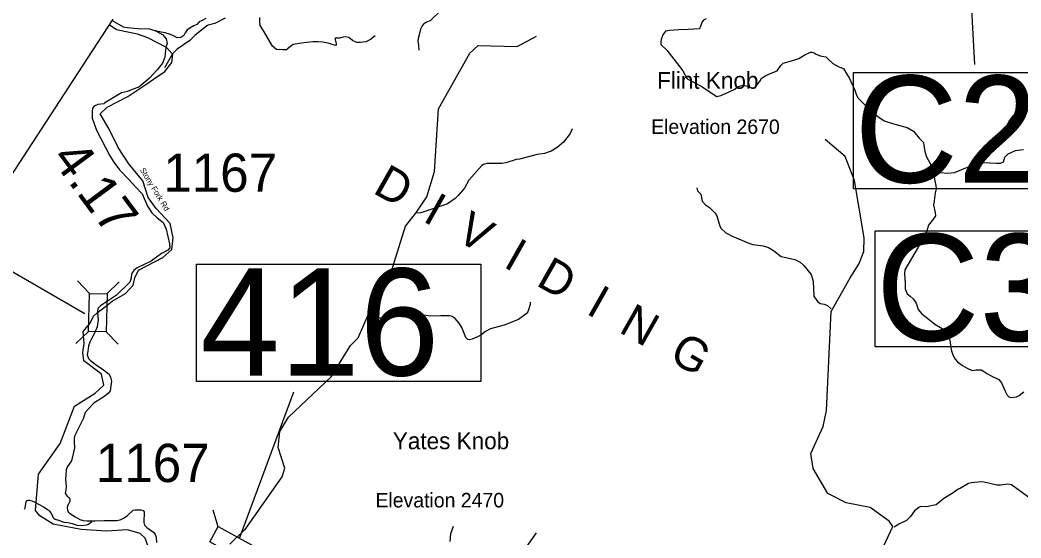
# Model space of a CAD drawing. Extents: x 1248224 to 1454986, y 825081 to 985870.
# Drawn here: x 1271332 to 1284414, y 889575 to 896350 of the extents above; entities that cross this region are included whole.
import ezdxf

# ---------------------------------------------------------------- set-up
doc = ezdxf.new("R2010")
doc.units = 0
for name, color, linetype in [('Exist Boundary Political CountyLine', 7, 'Continuous'), ('Exist Geographical Mountain Summit Elevation Number Label', 7, 'Continuous'), ('Exist Geographical Mountain Summit Label', 7, 'Continuous'), ('Exist Hydrographic Creek Single Shore', 7, 'Continuous'), ('Exist Hydrographic Misc Water Feature', 7, 'Continuous'), ('Exist Road Non-System Type 51', 7, 'Continuous'), ('Exist Road Primary US Structure Culvert Number Label', 7, 'Continuous'), ('Exist Road Secondary Mileage Hundredths English Label', 7, 'Continuous'), ('Exist Road Secondary Structure Standard Bridge CELL', 7, 'Continuous'), ('Exist Road Secondary Structure Standard Bridge Number Label', 7, 'Continuous'), ('Exist Road Secondary Type 41 Attributed', 7, 'Continuous'), ('Exist Road Secondary Type 51 Label', 7, 'Continuous'), ('Exist Road Secondary Type 51 Number Label', 7, 'Continuous')]:
    doc.layers.add(name, color=color, linetype=linetype)

msp = doc.modelspace()

# ---------------------------------------------------------------- linework, layer by layer
at = {"layer": 'Exist Boundary Political CountyLine'}
msp.add_lwpolyline([(1272546, 896361), (1272209, 895845), (1272087, 895657), (1271079, 894112), (1270645, 893445), (1270071, 892565), (1269839, 892212), (1269310, 891394), (1268930, 890816), (1268447, 890082), (1267988, 889389), (1267175, 888171), (1266759, 887546), (1266505, 887166), (1265873, 886219), (1264802, 884614), (1263985, 883390), (1262147, 880635), (1261769, 880070), (1260071, 878961), (1254161, 875151), (1250985, 873104), (1248224, 871303)], dxfattribs=at)
at = {"layer": 'Exist Hydrographic Creek Single Shore'}
for points in [[(1273331, 895899), (1273248, 895990), (1273003, 896117), (1272866, 896164), (1272593, 896221), (1272496, 896285)], [(1272882, 893076), (1273200, 893243), (1273317, 893347), (1273332, 893499), (1273293, 893688), (1273113, 893884), (1273008, 894027), (1272938, 894248), (1272752, 894469), (1272615, 894681), (1272496, 894923), (1272379, 895121), (1272472, 895208), (1272739, 895351), (1272991, 895514), (1273074, 895574), (1273226, 895677), (1273316, 895794), (1273331, 895899), (1273244, 895992)], [(1282587, 889398), (1282737, 889726), (1282689, 889796), (1282443, 889975), (1282128, 890034), (1281889, 890157), (1281697, 890486), (1281668, 890680), (1281827, 891035), (1281874, 891241), (1281931, 892539), (1282183, 892978), (1282296, 893156), (1282359, 893322), (1282363, 893499), (1282240, 894250), (1282114, 894565), (1281853, 894786)], [(1272346, 892523), (1272429, 892584), (1272538, 892672), (1272711, 892774), (1272810, 892882), (1272832, 892976), (1272882, 893076)], [(1272165, 891894), (1272154, 892000), (1272172, 892118), (1272159, 892276), (1272250, 892385), (1272293, 892478), (1272346, 892523)], [(1273750, 889148), (1273089, 889381), (1273008, 889465), (1272969, 889574), (1272903, 889634), (1272738, 889680), (1272462, 889663), (1272129, 889686), (1271764, 889756), (1271592, 889867), (1271535, 889934), (1271572, 890410), (1271857, 890811), (1272044, 891300), (1272315, 891468), (1272426, 891573), (1272396, 891716), (1272165, 891894)], [(1274075, 889493), (1274272, 889686), (1274274, 889688)]]:
    msp.add_lwpolyline(points, dxfattribs=at)
at = {"layer": 'Exist Hydrographic Misc Water Feature'}
for points in [[(1274011, 896376), (1273877, 896304), (1273792, 896284), (1273772, 896272), (1273615, 896148), (1273553, 896080), (1273386, 895970), (1273326, 895907), (1273218, 895724)], [(1274274, 889688), (1274756, 890375), (1274792, 890490), (1274707, 890757), (1274729, 890967), (1274842, 891155), (1275397, 891685), (1275649, 892094), (1275751, 892194), (1275885, 892502), (1276145, 892925), (1276371, 893652), (1276504, 893822), (1276647, 894037), (1276747, 894370), (1276801, 895186), (1277211, 895917), (1277321, 896016), (1277830, 896003), (1278083, 896139)], [(1284168, 894898), (1284229, 894967), (1284253, 895017), (1284315, 895101), (1284498, 895214)], [(1284168, 894898), (1284229, 894967), (1284253, 895017), (1284315, 895101), (1284498, 895214)], [(1278548, 894926), (1278523, 894867), (1278434, 894751), (1278352, 894681), (1278275, 894635), (1278186, 894603), (1278090, 894589), (1277860, 894529), (1277818, 894526), (1277681, 894483), (1277628, 894472), (1277432, 894471), (1277388, 894461), (1277368, 894449), (1277197, 894255), (1277142, 894152), (1277060, 894056), (1277019, 894017), (1276919, 893947), (1276883, 893931), (1276572, 893828), (1276504, 893822)], [(1280177, 894156), (1280188, 894116), (1280230, 894070), (1280248, 893980), (1280289, 893933), (1280344, 893896), (1280415, 893824), (1280438, 893787), (1280477, 893654), (1280496, 893625), (1280558, 893568), (1280637, 893522), (1280855, 893431), (1280909, 893413), (1281045, 893398), (1281112, 893376), (1281179, 893337), (1281281, 893258), (1281456, 893216), (1281528, 893182), (1281577, 893137), (1281670, 893022), (1281696, 892934), (1281705, 892738), (1281755, 892668), (1281791, 892643), (1281842, 892634), (1281886, 892617), (1281935, 892571)], [(1278000, 892660), (1277998, 892628), (1277967, 892535), (1277947, 892508), (1277845, 892434), (1277661, 892360), (1277480, 892311), (1277415, 892276), (1277353, 892227), (1277303, 892201), (1277240, 892175), (1277204, 892167), (1277184, 892172), (1277156, 892197), (1277104, 892330), (1277073, 892386), (1277020, 892444), (1276981, 892471), (1276945, 892480), (1276833, 892482), (1276697, 892476), (1276577, 892495), (1276485, 892485), (1276412, 892461), (1276269, 892472), (1276164, 892469), (1276036, 892452), (1276012, 892453), (1275992, 892461), (1275941, 892494), (1275885, 892502)], [(1284593, 890047), (1284288, 890272), (1284240, 890281), (1284148, 890266), (1284100, 890267), (1283913, 890309), (1283853, 890307), (1283765, 890297), (1283728, 890286), (1283610, 890218), (1283594, 890215), (1283527, 890165), (1283405, 890090), (1283303, 890008), (1283178, 889981), (1283106, 889987), (1283078, 889975), (1283021, 889929), (1282969, 889856), (1282916, 889806), (1282819, 889756), (1282758, 889715)], [(1276992, 889725), (1276957, 889630), (1276947, 889530)], [(1276458, 885104), (1276385, 885740), (1276213, 886210), (1276217, 886377), (1276325, 886861), (1276414, 886915), (1276860, 887060), (1277285, 887393), (1277703, 887792), (1277945, 888119), (1278137, 888466), (1278132, 888614), (1278059, 888717), (1277895, 888822), (1277792, 889024), (1277797, 889241), (1278082, 889642)]]:
    msp.add_lwpolyline(points, dxfattribs=at)
at = {"layer": 'Exist Road Non-System Type 51'}
for points in [[(1277521, 896794), (1277396, 896813), (1277239, 896817), (1277112, 896800), (1277030, 896765), (1276969, 896720), (1276927, 896664), (1276899, 896624), (1276878, 896579), (1276843, 896514), (1276807, 896466), (1276794, 896436), (1276735, 896381), (1276691, 896341), (1276642, 896321), (1276605, 896295), (1276588, 896272), (1276567, 896230), (1276550, 896156), (1276536, 896107), (1276532, 896079), (1276541, 896018), (1276545, 895955)], [(1275975, 896142), (1275911, 896094), (1275850, 896065), (1275781, 896054), (1275734, 896056), (1275676, 896082), (1275627, 896122), (1275589, 896130), (1275553, 896124), (1275505, 896113), (1275482, 896113), (1275456, 896113), (1275448, 896100), (1275459, 896065), (1275465, 896031), (1275454, 896018), (1275412, 896031), (1275357, 896048), (1275290, 896060), (1275229, 896065), (1275160, 896065), (1275082, 896056), (1275012, 896048), (1274953, 896039), (1274903, 896029), (1274865, 896004), (1274829, 895974), (1274814, 895960), (1274764, 895960), (1274683, 895966), (1274633, 896008), (1274521, 896193), (1274471, 896279), (1274467, 896334), (1274467, 896384)], [(1273762, 896370), (1273711, 896345), (1273671, 896324), (1273642, 896292), (1273602, 896273), (1273551, 896244), (1273516, 896222), (1273492, 896182), (1273471, 896147), (1273433, 896122), (1273385, 896117), (1273345, 896138), (1273299, 896161), (1273229, 896182), (1273175, 896191), (1273101, 896208)], [(1280301, 896363), (1280264, 896347), (1280248, 896327), (1280223, 896269), (1280212, 896235), (1280064, 896226), (1279940, 896223), (1279819, 896214), (1279769, 896202), (1279734, 896155), (1279710, 896093), (1279707, 896066), (1279707, 896039), (1279710, 896025), (1279784, 895954), (1279937, 895759), (1279996, 895685), (1280050, 895581)], [(1280941, 895473), (1281009, 895558), (1281020, 895585), (1281077, 895623), (1281147, 895656), (1281227, 895685), (1281274, 895756), (1281307, 895786), (1281443, 895824), (1281511, 895848), (1281587, 895895), (1281664, 895928), (1281679, 895928), (1281711, 895922), (1281738, 895904), (1281788, 895883), (1281815, 895875), (1281865, 895866), (1281883, 895845), (1281956, 895783), (1282032, 895739), (1282094, 895715), (1282124, 895665), (1282174, 895585), (1282207, 895508), (1282236, 895446), (1282266, 895367), (1282286, 895328), (1282310, 895302), (1282381, 895231), (1282481, 895136), (1282555, 895077), (1282625, 895033), (1282734, 894998), (1282926, 894944), (1283008, 894894), (1283085, 894803), (1283138, 894749), (1283144, 894714), (1283156, 894631), (1283180, 894560), (1283221, 894484), (1283265, 894373)], [(1280050, 895581), (1280236, 895484), (1280439, 895351)], [(1280439, 895351), (1280489, 895363), (1280598, 895411), (1280675, 895446), (1280708, 895476), (1280746, 895490), (1280784, 895496), (1280840, 895485), (1280846, 895485), (1280870, 895470), (1280911, 895464), (1280941, 895473)], [(1283265, 894373), (1283360, 894354), (1283453, 894345), (1283546, 894354), (1283834, 894472), (1283910, 894485), (1284003, 894480), (1284092, 894476), (1284147, 894476), (1284185, 894497), (1284202, 894557), (1284248, 894599), (1284341, 894641), (1284447, 894658)], [(1283265, 894373), (1283288, 894246), (1283300, 894184), (1283306, 894140), (1283294, 894089), (1283277, 893986), (1283271, 893927), (1283294, 893832), (1283297, 893788), (1283271, 893750), (1283206, 893667), (1283182, 893590), (1283070, 893377), (1282896, 893081), (1282893, 893033), (1282899, 892909), (1282902, 892832), (1282928, 892767), (1282967, 892738), (1283005, 892702), (1283044, 892646), (1283070, 892563), (1283117, 892505), (1283197, 892446), (1283288, 892370), (1283362, 892328), (1283436, 892284), (1283462, 892254), (1283480, 892219), (1283480, 892175), (1283489, 892139), (1283492, 892083), (1283507, 892021), (1283524, 891971), (1283554, 891915), (1283583, 891878)], [(1283583, 891878), (1283648, 891830), (1283712, 891798), (1283774, 891768), (1283804, 891771), (1283828, 891774), (1283893, 891774), (1283937, 891748), (1283975, 891724), (1284025, 891697), (1284123, 891650), (1284158, 891606), (1284211, 891485), (1284235, 891443), (1284253, 891423), (1284282, 891414), (1284356, 891423), (1284392, 891440), (1284451, 891488)], [(1271390, 889953), (1271399, 889971), (1271405, 889999), (1271408, 890023), (1271410, 890049), (1271420, 890061), (1271437, 890070), (1271457, 890072), (1271484, 890061), (1271526, 890042), (1271572, 890017), (1271637, 889982), (1271698, 889945), (1271718, 889928), (1271733, 889906), (1271751, 889876), (1271762, 889848), (1271774, 889833), (1271792, 889821), (1271836, 889808), (1271903, 889783), (1271955, 889776), (1272011, 889763), (1272080, 889745), (1272132, 889740), (1272164, 889741), (1272201, 889747), (1272219, 889754), (1272271, 889791)]]:
    msp.add_lwpolyline(points, dxfattribs=at)
at = {"layer": 'Exist Road Primary US Structure Culvert Number Label'}
msp.add_line((1283619, 899049), (1283808, 895770), dxfattribs=at)
for points in [[(1282224, 895662), (1286206, 895662), (1286206, 894143), (1282224, 894143)], [(1282506, 893594), (1286488, 893594), (1286488, 892074), (1282506, 892074)]]:
    msp.add_lwpolyline(points, close=True, dxfattribs=at)
at = {"layer": 'Exist Road Secondary Structure Standard Bridge CELL'}
for p, q in [((1272239, 892774), (1272082, 892937)), ((1272465, 892768), (1272629, 892925)), ((1272063, 892121), (1272227, 892278)), ((1272615, 892109), (1272458, 892273)), ((1273921, 889722), (1273858, 889939))]:
    msp.add_line(p, q, dxfattribs=at)
for points in [[(1272227, 892278), (1272238, 892774), (1272469, 892768), (1272458, 892273)], [(1274244, 889283), (1273811, 889523), (1273923, 889725), (1274357, 889485)]]:
    msp.add_lwpolyline(points, close=True, dxfattribs=at)
at = {"layer": 'Exist Road Secondary Structure Standard Bridge Number Label'}
for p, q in [((1272178, 892506), (1268930, 894384)), ((1274206, 889581), (1274912, 891488))]:
    msp.add_line(p, q, dxfattribs=at)
msp.add_lwpolyline([(1273637, 893157), (1277353, 893157), (1277353, 891621), (1273637, 891621)], close=True, dxfattribs=at)
at = {"layer": 'Exist Road Secondary Type 41 Attributed'}
for points in [[(1272535, 896344), (1272681, 896262), (1272735, 896250), (1272865, 896238), (1273026, 896235), (1273101, 896208), (1273195, 896159), (1273243, 896105), (1273253, 896041), (1273239, 895995)], [(1273239, 895995), (1273225, 895863), (1273192, 895787), (1273125, 895699), (1273026, 895587), (1272886, 895472), (1272796, 895442), (1272738, 895414), (1272659, 895399), (1272439, 895267), (1272427, 895255), (1272349, 895243), (1272300, 895222), (1272279, 895197), (1272276, 895149), (1272276, 895067), (1272330, 894910), (1272506, 894575), (1272557, 894490), (1272633, 894390), (1272754, 894266), (1272839, 894169), (1272926, 894078), (1272999, 893915), (1273053, 893829), (1273122, 893762), (1273204, 893702), (1273241, 893614), (1273286, 893423), (1273289, 893372), (1273265, 893341), (1273180, 893296), (1273044, 893196), (1272862, 893108), (1272817, 893072), (1272790, 893032), (1272784, 892972), (1272765, 892923), (1272594, 892750), (1272385, 892612), (1272349, 892578), (1272343, 892547), (1272346, 892523)], [(1272346, 892523), (1272354, 892427), (1272342, 892338), (1272311, 892262), (1272264, 892180), (1272249, 892145), (1272228, 892089), (1272219, 892019), (1272210, 891969), (1272225, 891921), (1272249, 891901), (1272316, 891843), (1272407, 891787), (1272498, 891716), (1272514, 891678), (1272527, 891625), (1272520, 891567), (1272508, 891501), (1272485, 891463), (1272443, 891433), (1272402, 891404), (1272302, 891345), (1272227, 891265), (1272182, 891215), (1272160, 891144), (1272045, 890906), (1272041, 890878), (1272039, 890839), (1272045, 890754), (1272027, 890675), (1272003, 890584), (1271950, 890510), (1271934, 890468), (1271927, 890341), (1271934, 890250), (1271929, 890203), (1271921, 890162), (1271933, 890141), (1271946, 890124), (1271973, 890107), (1271983, 890083), (1271983, 890054), (1271971, 890025), (1271952, 889995), (1271946, 889974), (1271950, 889938), (1271962, 889916), (1271980, 889898), (1272052, 889851), (1272112, 889818), (1272157, 889804), (1272204, 889801), (1272313, 889801), (1272431, 889803), (1272518, 889804), (1272597, 889803), (1272641, 889814), (1272686, 889835), (1272733, 889867), (1272809, 889939), (1272836, 889945), (1272912, 889945), (1272942, 889936), (1272954, 889918), (1272953, 889882), (1272948, 889814), (1272950, 889777), (1272960, 889745), (1272989, 889712), (1273075, 889650), (1273098, 889619), (1273111, 889584), (1273117, 889516)]]:
    msp.add_lwpolyline(points, dxfattribs=at)

# ---------------------------------------------------------------- texts
at = {"layer": 'Exist Geographical Mountain Summit Elevation Number Label'}
for s, p in [('Elevation 2670', (1279580, 894859)), ('Elevation 2470', (1275977, 889975))]:
    msp.add_text(s, height=190, dxfattribs=at).set_placement(p)
at = {"layer": 'Exist Geographical Mountain Summit Label'}
for s, p in [('Flint Knob', (1279658, 895450)), ('Yates Knob', (1276204, 890736))]:
    msp.add_text(s, height=220, dxfattribs=at).set_placement(p)
msp.add_text('D  I  V  I  D  I  N  G', height=440, rotation=330.4742, dxfattribs=at).set_placement((1275928, 894096))
at = {"layer": 'Exist Road Primary US Structure Culvert Number Label'}
for s, p in [('C27', (1282237, 894222)), ('C38', (1282519, 892154))]:
    msp.add_text(s, height=1400, dxfattribs=at).set_placement(p)
at = {"layer": 'Exist Road Secondary Mileage Hundredths English Label'}
msp.add_text('4.17', height=500, rotation=306.5443, dxfattribs=at).set_placement((1271730, 894537))
at = {"layer": 'Exist Road Secondary Structure Standard Bridge Number Label'}
msp.add_text('416', height=1400, dxfattribs=at).set_placement((1273687, 891700))
at = {"layer": 'Exist Road Secondary Type 51 Label'}
msp.add_text('Stony Fork Rd', height=75, rotation=301.3062, dxfattribs=at).set_placement((1272895, 894390))
at = {"layer": 'Exist Road Secondary Type 51 Number Label'}
for p in [(1273204, 894103), (1272323, 890307)]:
    msp.add_text('1167', height=500, dxfattribs=at).set_placement(p)

doc.saveas('drawing.dxf')
